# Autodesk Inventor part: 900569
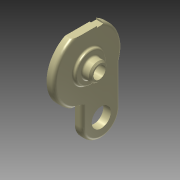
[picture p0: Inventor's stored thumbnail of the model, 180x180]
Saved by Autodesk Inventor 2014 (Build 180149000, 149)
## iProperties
Created: 2007-10
Part Number: 900569
Document SubType Name: Modeling
Designer: TH
Density: 1.13 g/cm^3
Mass: 11.4717 g
Surface Area: 58.4741 cm^2
Volume: 10.1519 cm^3
Material: Nylon Composite (Nylon, molybdenum disulphide)
Description: MOTOR SIDE MOUNT COVER
Appearance: Nylon 6
Component Category: Electrical
Author: TH
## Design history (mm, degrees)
sketch "Sketch1"
  geometry: L1 (0, 0)-(0, -22.5); L2 (0, -22.5)-(3, -22.5); L3 (5, -20.5)-(5, -11); L4 (6, -10)-(6, -10); L5 (7, -9)-(7, -7); L6 (8, -6)-(11.5, -6); L7 (12.5, -5)-(12.5, 0); L8 (12.5, 0)-(0, 0); L9 (11.5, -6)-(12.5, -5); A1 r 2 centre (3, -20.5) between (3, -22.5) and (5, -20.5); A2 r 1 centre (6, -11) between (6, -10) and (5, -11); A3 r 1 centre (6, -9) between (6, -10) and (7, -9); A4 r 1 centre (8, -7) between (8, -6) and (7, -7); 4 further points
  constraints: 18 end point, 8 point on circle, 8 point on line, 8 tangent, 6 parallel, 4 centre point, 2 equal radius, 1 perpendicular, 1 vertical
  dimensions: "d0" = 22.5 distance of L1.start L1.end; "d1" = 5 distance of L1.end point (5, -22.5); "d2" = 2 distance of point (5, -10) point (7, -10); "d3" = 6 distance between parallel lines of L8 L6; "d4" = 12.5 distance between parallel lines of L1 L7; "d5" = 2 radius of A1; "d6" = 1 radius of A2; "d7" = 1 distance of L6.end point (12.5, -6); "d8" = 1 distance of L7.start point (12.5, -6) (= d7); "d9" = 10 distance from line of L8 L4.end
revolve "Revolution1" sketch "Sketch1" stored, may be unused: angle "d10" = 90 deg
sketch "Sketch2"
  geometry: L1 (-20, -10.308)-(-20, 10.308); L2 (20, 10.308)-(20, -10.308); L3 (0, 31.5)-(0, -31.5) reference; A1 r 22.5 centre (0, 0) between (20, -10.308) and (-20, 10.308) reference
  constraints: 4 end point, 4 point on circle, 2 parallel, 1 vertical
  dimensions: "d11" = 40 distance of L2.end L1.start; "d12" = 20 distance between parallel lines of L2 L3
extrude "Extrusion1" cut sketch "Sketch2" stored distance "d13" = 10; taper "d14" = 0 deg
sketch "Sketch3"
  geometry: C1 r 5 at (0, 0) reference; C2 r 4 at (0, 0)
  constraints: 1 centre point, 1 coincident
  dimensions: "d15" = 8 diameter of C2
extrude "Extrusion2" cut sketch "Sketch3" stored distance "d16" = 10; taper "d17" = 0 deg
sketch "Sketch4"
  geometry: L1 (18.995, 10.308)-(20, 10.308); L2 (20, 5.938)-(18.995, 5.938); L3 (18.995, 5.938)-(18.995, 10.308); L4 (-20, 10.308)-(-20, -10.308) reference; L5 (20, -10.308)-(20, 10.308) reference; L6 (20, 10.308)-(20, 5.938); L7 (-20, -5.938)-(-20, -10.308); L8 (-20, -10.308)-(-18.995, -10.308); L9 (-18.995, -10.308)-(-18.995, -5.938); L10 (-18.995, -5.938)-(-20, -5.938)
  constraints: 16 end point, 5 perpendicular, 2 parallel, 2 point on line
  dimensions: "d18" = 4.37 distance of L2.end L1.start; "d25" = 1.005 distance of L9.end L7.start (= d24); "d26" = 4.37 distance of L8.end L9.end (= d18); "d44" = 1.005 distance between parallel lines of L5 L3
extrude "Extrusion3" cut sketch "Sketch4" stored distance "d22" = 10; taper "d23" = 0 deg
sketch "Sketch5"
  geometry: L1 (18.995, 5.938)-(18.995, 10.308) reference; L2 (-20, -3.777)-(-33.813, -3.777); L3 (-46.313, 8.723)-(-46.313, 8.723); L4 (-33.813, 21.223)-(-7.471, 21.223); L5 (20, 5.938)-(18.995, 5.938) reference; L6 (-20, -3.777)-(-15, -3.777); L7 (-15, -3.777)-(-15, 0); L8 (-7.471, 21.223)-(-4.981, 14.149); L9 (-20, 10.308)-(-20, -5.938) reference; C1 r 6.33 at (-33.813, 8.723); C2 r 4 at (0, 0) reference; A1 r 12.5 centre (-33.813, 8.723) between (-46.313, 8.723) and (-33.813, -3.777); A2 r 12.5 centre (-33.813, 8.723) between (-33.813, 21.223) and (-46.313, 8.723); A3 r 15 centre (0, 0) between (-4.981, 14.149) and (-15, 0); 1 further point
  constraints: 12 end point, 6 point on circle, 5 tangent, 4 centre point, 3 perpendicular, 2 coincident, 2 parallel, 1 concentric, 1 point on line
  dimensions: "d30" = 12.5 radius of A1; "d31" = 33.81283 horizontal distance of point (0, 0) A2.centre; "d32" = 8.72347 vertical distance of point (0, 0) A2.centre; "d33" = 12.66 diameter of C1; "d34" = 12.5 distance from line of A2.centre L2; "d39" = 5 distance between parallel lines of L9 L7; "d40" = 19.3927 deg angle of L9 L8
extrude "Extrusion4" join sketch "Sketch5" stored distance "d35" = 10; taper "d36" = 0 deg
fillet "Fillet2" dims "d41" = 2.033
fillet "Fillet3" dims "d42" = 1
fillet "Fillet4" dims "d43" = 5
sketch "Sketch6"
  geometry: L1 (-20, -4.777)-(-20, -5.938) reference; L2 (-20, -5.938)-(-18.995, -5.938) reference; L3 (18.995, 10.308)-(20, 10.308) reference; L4 (-33.813, 8.723)-(-33.813, -2.527); L5 (-33.813, -2.527)-(-21.313, -2.527); L6 (-33.813, 0.473)-(-21.313, 0.473); L7 (-21.313, -2.527)-(-21.313, 0.473); L8 (-33.813, 8.723)-(-33.813, 16.973); L9 (-33.813, 16.973)-(-15.813, 16.973); L10 (-15.813, 16.973)-(-15.813, 19.973); L11 (-33.813, 19.973)-(-15.813, 19.973); L12 (-33.813, 16.973)-(-33.813, 19.973); L13 (-42.024, 7.924)-(-45.013, 7.663); L14 (-35.405, 0.629)-(-35.926, -2.326); L15 (-42.024, 9.523)-(-45.013, 9.784); L16 (-35.405, 16.818)-(-35.926, 19.773); C1 r 6.33 at (-33.813, 8.723) reference; A1 r 12.5 centre (-33.813, 8.723) between (-33.813, 21.223) and (-33.813, -3.777) reference; A2 r 8.25 centre (-33.813, 8.723) between (-35.405, 16.818) and (-42.024, 9.523); A3 r 8.25 centre (-33.813, 8.723) between (-42.024, 7.924) and (-35.405, 0.629); A4 r 11.25 centre (-33.813, 8.723) between (-35.926, 19.773) and (-45.013, 9.784); A5 r 11.25 centre (-33.813, 8.723) between (-45.013, 7.663) and (-35.926, -2.326)
  constraints: 26 end point, 8 point on circle, 7 perpendicular, 4 centre point, 4 tangent, 3 coincident, 3 parallel, 1 point on line
  dimensions: "d47" = 12.5 distance between parallel lines of L7 L4; "d48" = 18 distance between parallel lines of L8 L10; "d52" = 5 deg angle of L2 L13; "d53" = 10 deg angle of L4 L14; "d54" = 10 deg angle of L15 L13; "d55" = 10 deg angle of L16 L12; "d56" = 11.25 radius of A5; "d57" = 3 radial gap between concentric circles of A3 A5; "d58" = 3 radial gap between concentric circles of A4 A2 (= d57); "d59" = 11.25 radius of A4; "d60" = 1.59844 distance of L13.start L15.start; "d61" = 1.59235 distance from line of L4 L14.start; "d62" = 1.59235 distance from line of L8 L16.start; "d63" = 0.79922 vertical distance of L13.start C1.centre
extrude "Extrusion5" cut sketch "Sketch6" distance "d64" = 3; taper "d65" = 0 deg
fillet "Fillet5" dims "d66" = 1.03
body "Solid1"
other parameters: "d24" = 1.005, "d45" = 1.25, "d46" = 1.25, "d49" = 10 deg, "d50" = 10 deg (= d49), "d51" = 10 deg (= d49)
